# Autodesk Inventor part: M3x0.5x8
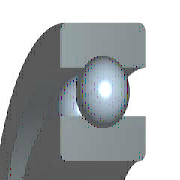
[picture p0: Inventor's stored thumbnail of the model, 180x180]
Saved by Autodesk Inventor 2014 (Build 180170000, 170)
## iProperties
Created: 2009-02
Part Number: M3x0.5x8
Material: 강, 연강
Description: 깊은 그루브 볼 베어링
Document SubType Name: Modeling
Standard: KS B 2023
Designer: KYOUNG IL JANG
Standards Organization: KS
Language: ko-KR
Size Designation: 6201 - 12 x 32 x 10
Categories: <MemberInstance><Categories><Category DisplayName="샤프트 부품" InternalName="7f7aeb1f-a693-4053-b835-cee3144e0d98" Mnemonic="SHFT"><Category DisplayName="베어링" Inter
Density: 7.86 g/cm^3
Mass: 36.8026 g
Surface Area: 42.5728 cm^2
Volume: 4.68226 cm^3
Vendor: CBT Solutions
Appearance: 강철
Company: 한국ATC센터
IsCustomPart: 1
Author: KYOUNG IL JANG
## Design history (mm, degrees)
sketch "스케치" dims "d0" = 5.2 (= -0.26 x WD + 0.26 x BD)
  geometry: L1 (2.4, 11)-(7.6, 11); L2 (5, 11)-(5, 8.4); L3 (5, 11)-(5, 13.6); L4 (3.068, 9.26)-(0, 9.26); L5 (0, 6)-(10, 6); L6 (3.068, 12.74)-(0, 12.74); L7 (0, 16)-(10, 16); L8 (10, 6)-(10, 9.26); L9 (6.932, 9.26)-(10, 9.26); L10 (6.932, 12.74)-(10, 12.74); L11 (10, 16)-(10, 12.74); L12 (-1.4, 0)-(8.4, 0) reference; L13 (0, -0.3)-(0, 5.3) reference
  constraints: 22 end point, 4 point on line, 2 collinear, 2 perpendicular, 2 symmetric about line, 1 midpoint, 1 parallel, 14 other
  dimensions: "d9" = 12 diameter of L5 L12 (= WD); "d11" = 32 diameter of L7 L12 (= BD); "d12" = 10 distance between parallel lines of L8 L13 (= KB); "d13" = 18.52 diameter of L9 L12 (= 0.326 x BD + 0.674 x WD)
revolve "본체" stored, may be unused: angle "d6" = 90 deg
revolve "볼" stored, may be unused: angle "d7" = 90 deg
pattern_circular "IDS_ARRAYBALL[SIMPL:T]" dims angle "d3" = 360 deg
body "Solid1"
fillet "모깎기1" dims "d1" = 0.6 (= KRS)
other parameters: "WD" = 12 [user parameter; used in 5 equation terms], "BD" = 32 [user parameter; used in 5 equation terms], "KB" = 10 [user parameter; used in 1 equation term], "KRS" = 0.6 [user parameter; used in 1 equation term], "d4" = 0, "d5" = 0, "d8" = 0, "d14" = 0, "d15" = 0, "BBA" = 0 [user parameter], "BC0" = 3100000 [user parameter], "BC" = 6890000 [user parameter], "BR" = 16 (= 0.5 x BD) [user parameter], "WR" = 6 (= 0.5 x WD) [user parameter]
